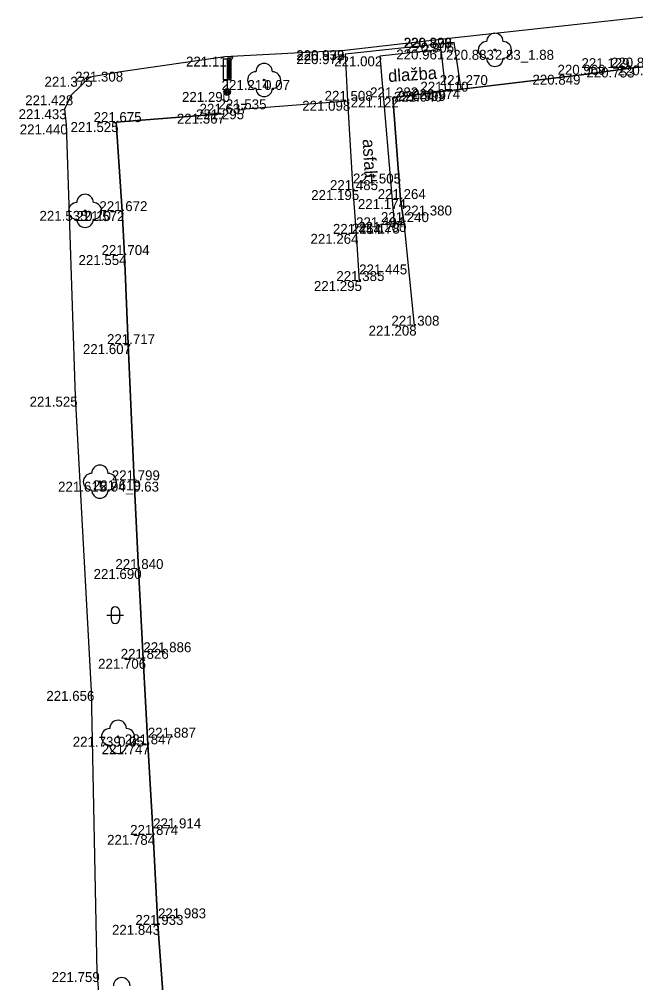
# Model space of a CAD drawing. Extents: x -599516 to -599132, y -1163668 to -1163119.
# Drawn here: x -599285.91 to -599267.3, y -1163526.85 to -1163497.76 of the extents above; entities that cross this region are included whole.
import ezdxf

# ---------------------------------------------------------------- set-up
doc = ezdxf.new("R2010")
doc.units = 0
for name, color, linetype in [('Bod-oznac1', 7, 'Continuous'), ('Bod-oznac2', 7, 'Continuous'), ('Bod-oznac3', 7, 'Continuous'), ('Bod-vyska1', 7, 'Continuous'), ('Bod-vyska2', 7, 'Continuous'), ('Bod-vyska3', 7, 'Continuous'), ('Z_cela-hrobu-dolni-linie', 7, 'Continuous'), ('Z_cela-hrobu-horni-linie', 7, 'Continuous'), ('Z_chodnik', 7, 'Continuous'), ('Z_komunikace', 7, 'Continuous'), ('Z_kultury-znacky', 7, 'Continuous'), ('Z_nove-stromy-prumer-kmene', 7, 'Continuous'), ('Z_obvod-kmene-spodek-ve-vysce1_2m', 7, 'Continuous'), ('Z_popis-budov-povrchu', 7, 'Continuous'), ('Z_povrchy-rozhrani-typu', 7, 'Continuous'), ('Z_stromy-kere', 7, 'Continuous'), ('Z_stromy-nove-vysazene', 7, 'Continuous'), ('Z_vol-lin-obrubnik', 7, 'Continuous'), ('Z_znacky-ostatni-orientacni-sloupek', 7, 'Continuous')]:
    doc.layers.add(name, color=color, linetype=linetype)

msp = doc.modelspace()

# ---------------------------------------------------------------- linework, layer by layer
at = {"layer": 'Bod-oznac1'}
for p, q in [((-599272.842, -1163498.312), (-599272.842, -1163498.312)), ((-599272.841, -1163498.321), (-599272.841, -1163498.321)), ((-599272.78, -1163498.461), (-599272.78, -1163498.461)), ((-599276.086, -1163498.689), (-599276.086, -1163498.689)), ((-599276.085, -1163498.698), (-599276.085, -1163498.698)), ((-599276.079, -1163498.81), (-599276.079, -1163498.81)), ((-599273.179, -1163498.668), (-599273.179, -1163498.668)), ((-599271.554, -1163498.679), (-599271.554, -1163498.679)), ((-599279.708, -1163498.883), (-599279.708, -1163498.883)), ((-599275.031, -1163498.874), (-599275.031, -1163498.874)), ((-599282.852, -1163499.337), (-599282.852, -1163499.337)), ((-599267.309, -1163499.213), (-599267.309, -1163499.213)), ((-599283.774, -1163499.492), (-599283.774, -1163499.492)), ((-599278.521, -1163499.59), (-599278.521, -1163499.59)), ((-599268.94, -1163499.43), (-599268.94, -1163499.43)), ((-599279.637, -1163499.95), (-599279.637, -1163499.95)), ((-599273.218, -1163499.942), (-599273.218, -1163499.942)), ((-599273.038, -1163499.92), (-599273.038, -1163499.92)), ((-599272.573, -1163499.865), (-599272.573, -1163499.865)), ((-599284.347, -1163500.051), (-599284.347, -1163500.051)), ((-599276.007, -1163500.217), (-599276.007, -1163500.217)), ((-599274.632, -1163500.114), (-599274.632, -1163500.114)), ((-599284.546, -1163500.471), (-599284.546, -1163500.471)), ((-599279.212, -1163500.474), (-599279.212, -1163500.474)), ((-599279.787, -1163500.607), (-599279.787, -1163500.607)), ((-599284.503, -1163500.932), (-599284.503, -1163500.932)), ((-599282.988, -1163500.86), (-599282.988, -1163500.86)), ((-599275.839, -1163502.913), (-599275.839, -1163502.913)), ((-599274.403, -1163503.184), (-599274.403, -1163503.184)), ((-599283.927, -1163503.541), (-599283.927, -1163503.541)), ((-599282.811, -1163503.549), (-599282.811, -1163503.549)), ((-599274.599, -1163503.924), (-599274.599, -1163503.924)), ((-599274.302, -1163503.88), (-599274.302, -1163503.88)), ((-599275.745, -1163504.235), (-599275.745, -1163504.235)), ((-599282.737, -1163504.875), (-599282.737, -1163504.875)), ((-599275.652, -1163505.659), (-599275.652, -1163505.659)), ((-599273.991, -1163507.007), (-599273.991, -1163507.007)), ((-599282.626, -1163507.564), (-599282.626, -1163507.564)), ((-599284.225, -1163509.15), (-599284.225, -1163509.15)), ((-599283.481, -1163511.717), (-599283.481, -1163511.717)), ((-599282.442, -1163511.676), (-599282.442, -1163511.676)), ((-599282.318, -1163514.355), (-599282.318, -1163514.355)), ((-599282.169, -1163517.066), (-599282.169, -1163517.066)), ((-599283.742, -1163518.035), (-599283.742, -1163518.035)), ((-599282.932, -1163519.42), (-599282.932, -1163519.42)), ((-599282.032, -1163519.647), (-599282.032, -1163519.647)), ((-599281.872, -1163522.382), (-599281.872, -1163522.382)), ((-599281.726, -1163525.099), (-599281.726, -1163525.099)), ((-599283.568, -1163526.525), (-599283.568, -1163526.525))]:
    msp.add_line(p, q, dxfattribs=at)
at = {"layer": 'Bod-oznac2'}
for p, q in [((-599267.309, -1163499.213), (-599267.309, -1163499.213)), ((-599268.94, -1163499.43), (-599268.94, -1163499.43)), ((-599273.218, -1163499.942), (-599273.218, -1163499.942)), ((-599276.007, -1163500.217), (-599276.007, -1163500.217)), ((-599274.632, -1163500.114), (-599274.632, -1163500.114)), ((-599279.212, -1163500.474), (-599279.212, -1163500.474)), ((-599279.787, -1163500.607), (-599279.787, -1163500.607)), ((-599282.988, -1163500.86), (-599282.988, -1163500.86)), ((-599275.839, -1163502.913), (-599275.839, -1163502.913)), ((-599274.403, -1163503.184), (-599274.403, -1163503.184)), ((-599282.811, -1163503.549), (-599282.811, -1163503.549)), ((-599274.302, -1163503.88), (-599274.302, -1163503.88)), ((-599275.745, -1163504.235), (-599275.745, -1163504.235)), ((-599282.737, -1163504.875), (-599282.737, -1163504.875)), ((-599275.652, -1163505.659), (-599275.652, -1163505.659)), ((-599273.991, -1163507.007), (-599273.991, -1163507.007)), ((-599282.626, -1163507.564), (-599282.626, -1163507.564)), ((-599282.442, -1163511.676), (-599282.442, -1163511.676)), ((-599282.318, -1163514.355), (-599282.318, -1163514.355)), ((-599282.169, -1163517.066), (-599282.169, -1163517.066)), ((-599282.032, -1163519.647), (-599282.032, -1163519.647)), ((-599281.872, -1163522.382), (-599281.872, -1163522.382)), ((-599281.726, -1163525.099), (-599281.726, -1163525.099))]:
    msp.add_line(p, q, dxfattribs=at)
at = {"layer": 'Bod-oznac3'}
for p, q in [((-599267.309, -1163499.213), (-599267.309, -1163499.213)), ((-599268.94, -1163499.43), (-599268.94, -1163499.43)), ((-599273.218, -1163499.942), (-599273.218, -1163499.942)), ((-599275.839, -1163502.913), (-599275.839, -1163502.913)), ((-599274.302, -1163503.88), (-599274.302, -1163503.88)), ((-599275.745, -1163504.235), (-599275.745, -1163504.235)), ((-599275.652, -1163505.659), (-599275.652, -1163505.659)), ((-599282.169, -1163517.066), (-599282.169, -1163517.066)), ((-599282.032, -1163519.647), (-599282.032, -1163519.647)), ((-599281.872, -1163522.382), (-599281.872, -1163522.382)), ((-599281.726, -1163525.099), (-599281.726, -1163525.099))]:
    msp.add_line(p, q, dxfattribs=at)
at = {"layer": 'Z_cela-hrobu-dolni-linie'}
msp.add_line((-599279.212, -1163500.474), (-599276.007, -1163500.217), dxfattribs=at)
for points in [[(-599274.302, -1163503.88), (-599274.403, -1163503.184), (-599274.632, -1163500.114), (-599273.218, -1163499.942), (-599273.038, -1163499.92), (-599272.573, -1163499.865), (-599268.94, -1163499.43), (-599267.309, -1163499.213), (-599266.378, -1163499.149), (-599265.631, -1163499.079), (-599264.347, -1163498.989), (-599262.858, -1163498.794), (-599262.329, -1163498.704), (-599260.501, -1163498.482), (-599256.173, -1163498.082)], [(-599279.787, -1163500.607), (-599282.988, -1163500.86), (-599282.811, -1163503.549), (-599282.737, -1163504.875), (-599282.626, -1163507.564), (-599282.442, -1163511.676), (-599282.318, -1163514.355), (-599282.169, -1163517.066), (-599282.032, -1163519.647), (-599281.872, -1163522.382), (-599281.726, -1163525.099), (-599281.531, -1163527.809)]]:
    msp.add_lwpolyline(points, dxfattribs=at)
at = {"layer": 'Z_cela-hrobu-horni-linie'}
for points in [[(-599266.378, -1163499.149), (-599267.309, -1163499.213), (-599267.309, -1163499.213), (-599268.94, -1163499.43), (-599268.94, -1163499.43), (-599273.218, -1163499.942), (-599273.218, -1163499.942), (-599274.632, -1163500.114), (-599274.403, -1163503.184), (-599274.302, -1163503.88), (-599274.302, -1163503.88), (-599273.991, -1163507.007)], [(-599279.212, -1163500.474), (-599276.007, -1163500.217), (-599275.839, -1163502.913), (-599275.839, -1163502.913), (-599275.745, -1163504.235), (-599275.745, -1163504.235), (-599275.652, -1163505.659), (-599275.652, -1163505.659)], [(-599274.433, -1163527.432), (-599277.687, -1163527.652), (-599277.687, -1163527.652), (-599278.332, -1163527.679), (-599278.332, -1163527.679), (-599281.531, -1163527.809), (-599281.726, -1163525.099), (-599281.726, -1163525.099), (-599281.872, -1163522.382), (-599281.872, -1163522.382), (-599282.032, -1163519.647), (-599282.032, -1163519.647), (-599282.169, -1163517.066), (-599282.169, -1163517.066), (-599282.318, -1163514.355), (-599282.442, -1163511.676), (-599282.626, -1163507.564), (-599282.737, -1163504.875), (-599282.811, -1163503.549), (-599282.988, -1163500.86), (-599279.787, -1163500.607)]]:
    msp.add_lwpolyline(points, dxfattribs=at)
at = {"layer": 'Z_chodnik'}
for points in [[(-599272.573, -1163499.865), (-599272.78, -1163498.461), (-599276.079, -1163498.81)], [(-599276.079, -1163498.81), (-599276.007, -1163500.217)], [(-599276.007, -1163500.217), (-599275.839, -1163502.913), (-599275.745, -1163504.235), (-599275.652, -1163505.659)], [(-599274.302, -1163503.88), (-599273.991, -1163507.007)]]:
    msp.add_lwpolyline(points, dxfattribs=at)
at = {"layer": 'Z_komunikace'}
for points in [[(-599283.774, -1163499.492), (-599282.852, -1163499.337), (-599279.708, -1163498.883), (-599276.086, -1163498.689), (-599272.842, -1163498.312), (-599264.739, -1163497.429), (-599258.515, -1163496.759), (-599251.636, -1163496.1), (-599246.298, -1163495.689)], [(-599283.774, -1163499.492), (-599284.347, -1163500.051), (-599284.546, -1163500.471), (-599284.503, -1163500.932), (-599284.225, -1163509.15), (-599283.742, -1163518.035), (-599283.568, -1163526.525), (-599282.85, -1163535.167), (-599282.562, -1163543.784), (-599281.789, -1163553.131), (-599281.327, -1163555.242), (-599281.398, -1163558.288)]]:
    msp.add_lwpolyline(points, dxfattribs=at)
at = {"layer": 'Z_kultury-znacky'}
for p, q in [((-599283.142, -1163515.62), (-599283.142, -1163515.87)), ((-599282.892, -1163515.62), (-599282.892, -1163515.87)), ((-599283.267, -1163515.745), (-599282.767, -1163515.745))]:
    msp.add_line(p, q, dxfattribs=at)
for centre, start, end in [((-599283.017, -1163515.62), 0, 180), ((-599283.017, -1163515.87), 180, 0)]:
    msp.add_arc(centre, 0.125, start, end, dxfattribs=at)
at = {"layer": 'Z_povrchy-rozhrani-typu'}
for points in [[(-599273.038, -1163499.92), (-599273.179, -1163498.668), (-599275.031, -1163498.874)], [(-599275.031, -1163498.874), (-599274.599, -1163503.924), (-599274.302, -1163503.88)]]:
    msp.add_lwpolyline(points, dxfattribs=at)
at = {"layer": 'Z_stromy-kere'}
for centre in [(-599271.554, -1163498.679), (-599283.481, -1163511.717)]:
    msp.add_circle(centre, 0.025, dxfattribs=at)
for centre, start, end in [((-599271.554, -1163498.429), 0, 180), ((-599271.804, -1163498.679), 90, 270), ((-599271.304, -1163498.679), 270, 90), ((-599271.554, -1163498.929), 180, 0), ((-599283.481, -1163511.467), 0, 180), ((-599283.731, -1163511.717), 90, 270), ((-599283.231, -1163511.717), 270, 90), ((-599283.481, -1163511.967), 180, 0), ((-599282.821, -1163526.941), 0, 180)]:
    msp.add_arc(centre, 0.25, start, end, dxfattribs=at)
at = {"layer": 'Z_stromy-nove-vysazene'}
for centre in [(-599278.521, -1163499.59), (-599283.927, -1163503.541), (-599282.932, -1163519.42)]:
    msp.add_circle(centre, 0.025, dxfattribs=at)
for centre, start, end in [((-599278.521, -1163499.34), 0, 180), ((-599278.771, -1163499.59), 90, 270), ((-599278.271, -1163499.59), 270, 90), ((-599278.521, -1163499.84), 180, 0), ((-599283.927, -1163503.291), 0, 180), ((-599284.177, -1163503.541), 90, 270), ((-599283.677, -1163503.541), 270, 90), ((-599283.927, -1163503.791), 180, 0), ((-599283.182, -1163519.42), 90, 270), ((-599282.932, -1163519.17), 0, 180), ((-599282.682, -1163519.42), 270, 90), ((-599282.932, -1163519.67), 180, 0)]:
    msp.add_arc(centre, 0.25, start, end, dxfattribs=at)
at = {"layer": 'Z_vol-lin-obrubnik'}
msp.add_lwpolyline([(-599246.297, -1163495.698), (-599251.635, -1163496.109), (-599258.514, -1163496.768), (-599264.738, -1163497.438), (-599272.841, -1163498.321), (-599276.085, -1163498.698)], dxfattribs=at)
at = {"layer": 'Z_znacky-ostatni-orientacni-sloupek'}
for p, q in [((-599279.762, -1163498.95), (-599279.762, -1163499.575)), ((-599279.762, -1163498.95), (-599279.637, -1163498.95)), ((-599279.762, -1163499.575), (-599279.637, -1163499.575)), ((-599279.637, -1163499.575), (-599279.637, -1163499.85))]:
    msp.add_line(p, q, dxfattribs=at)
for points in [[(-599279.637, -1163499.575), (-599279.512, -1163499.575), (-599279.512, -1163498.95), (-599279.637, -1163498.95)], [(-599279.595, -1163499.532), (-599279.554, -1163499.532), (-599279.554, -1163498.992), (-599279.595, -1163498.992)]]:
    msp.add_lwpolyline(points, close=True, dxfattribs=at)
for radius in [0.1, 0.065, 0.03]:
    msp.add_circle((-599279.637, -1163499.95), radius, dxfattribs=at)

# ---------------------------------------------------------------- texts
at = {"layer": 'Bod-vyska1'}
for s, p in [('220.829', (-599274.31, -1163498.612)), ('220.896', (-599274.298, -1163498.621)), ('220.906', (-599274.235, -1163498.761)), ('220.932', (-599277.554, -1163498.989)), ('220.977', (-599277.551, -1163499.11)), ('220.979', (-599277.544, -1163498.998)), ('220.961', (-599274.532, -1163498.968)), ('220.883', (-599273.034, -1163498.979)), ('221.117', (-599280.88, -1163499.183)), ('221.002', (-599276.405, -1163499.174)), ('221.308', (-599284.228, -1163499.637)), ('220.753', (-599268.79, -1163499.513)), ('220.776', (-599267.85, -1163499.449)), ('221.375', (-599285.153, -1163499.792)), ('221.214', (-599279.806, -1163499.89)), ('220.849', (-599270.42, -1163499.73)), ('221.290', (-599281.001, -1163500.25)), ('221.040', (-599274.603, -1163500.242)), ('220.999', (-599274.484, -1163500.22)), ('220.974', (-599274.054, -1163500.165)), ('221.428', (-599285.736, -1163500.351)), ('221.098', (-599277.371, -1163500.517)), ('221.122', (-599275.906, -1163500.414)), ('221.433', (-599285.935, -1163500.771)), ('221.295', (-599280.578, -1163500.774)), ('221.525', (-599284.366, -1163501.16)), ('221.367', (-599281.155, -1163500.907)), ('221.440', (-599285.901, -1163501.232)), ('221.195', (-599277.101, -1163503.213)), ('221.174', (-599275.69, -1163503.484)), ('221.535', (-599285.305, -1163503.841)), ('221.572', (-599284.19, -1163503.849)), ('221.178', (-599275.874, -1163504.224)), ('221.200', (-599275.676, -1163504.18)), ('221.264', (-599277.123, -1163504.535)), ('221.554', (-599284.126, -1163505.175)), ('221.295', (-599277.018, -1163505.959)), ('221.208', (-599275.367, -1163507.307)), ('221.607', (-599283.992, -1163507.864)), ('221.525', (-599285.603, -1163509.45)), ('221.615', (-599284.743, -1163512.017)), ('221.619', (-599283.693, -1163511.976)), ('221.690', (-599283.671, -1163514.655)), ('221.706', (-599283.535, -1163517.366)), ('221.656', (-599285.097, -1163518.335)), ('221.739', (-599284.3, -1163519.72)), ('221.747', (-599283.425, -1163519.947)), ('221.784', (-599283.263, -1163522.682)), ('221.843', (-599283.115, -1163525.399)), ('221.759', (-599284.936, -1163526.825))]:
    msp.add_text(s, height=0.3, dxfattribs=at).set_placement(p)
at = {"layer": 'Bod-vyska2'}
for s, p in [('220.883', (-599268.049, -1163499.213)), ('220.969', (-599269.663, -1163499.43)), ('221.110', (-599273.802, -1163499.942)), ('221.508', (-599276.695, -1163500.217)), ('221.282', (-599275.321, -1163500.114)), ('221.535', (-599279.901, -1163500.474)), ('221.675', (-599283.672, -1163500.86)), ('221.637', (-599280.471, -1163500.607)), ('221.485', (-599276.533, -1163502.913)), ('221.264', (-599275.092, -1163503.184)), ('221.672', (-599283.495, -1163503.549)), ('221.240', (-599274.996, -1163503.88)), ('221.454', (-599276.445, -1163504.235)), ('221.704', (-599283.431, -1163504.875)), ('221.385', (-599276.341, -1163505.659)), ('221.308', (-599274.679, -1163507.007)), ('221.717', (-599283.265, -1163507.564)), ('221.799', (-599283.12, -1163511.676)), ('221.840', (-599283.012, -1163514.355)), ('221.826', (-599282.852, -1163517.066)), ('221.847', (-599282.727, -1163519.647)), ('221.874', (-599282.567, -1163522.382)), ('221.933', (-599282.409, -1163525.099))]:
    msp.add_text(s, height=0.3, dxfattribs=at).set_placement(p)
at = {"layer": 'Bod-vyska3'}
for s, p in [('221.129', (-599268.94, -1163499.23)), ('221.270', (-599273.218, -1163499.742)), ('221.505', (-599275.839, -1163502.713)), ('221.380', (-599274.302, -1163503.68)), ('221.494', (-599275.745, -1163504.035)), ('221.445', (-599275.652, -1163505.459)), ('221.886', (-599282.169, -1163516.866)), ('221.887', (-599282.032, -1163519.447)), ('221.914', (-599281.872, -1163522.182)), ('221.983', (-599281.726, -1163524.899))]:
    msp.add_text(s, height=0.3, dxfattribs=at).set_placement(p)
at = {"layer": 'Z_nove-stromy-prumer-kmene'}
for s, p in [('0.07', (-599278.521, -1163499.89)), ('0.10', (-599283.927, -1163503.841)), ('0.05', (-599282.932, -1163519.72))]:
    msp.add_text(s, height=0.3, dxfattribs=at).set_placement(p)
at = {"layer": 'Z_obvod-kmene-spodek-ve-vysce1_2m'}
for s, p in [('2.83_1.88', (-599271.554, -1163498.979)), ('0.94_0.63', (-599283.481, -1163512.017))]:
    msp.add_text(s, height=0.3, dxfattribs=at).set_placement(p)
at = {"layer": 'Z_popis-budov-povrchu'}
for s, rotation, p in [('dlažba', 3.9346, (-599274.766, -1163499.654)), ('asfalt', 273.4503, (-599275.552, -1163501.382))]:
    msp.add_text(s, height=0.375, rotation=rotation, dxfattribs=at).set_placement(p)

doc.saveas('drawing.dxf')
